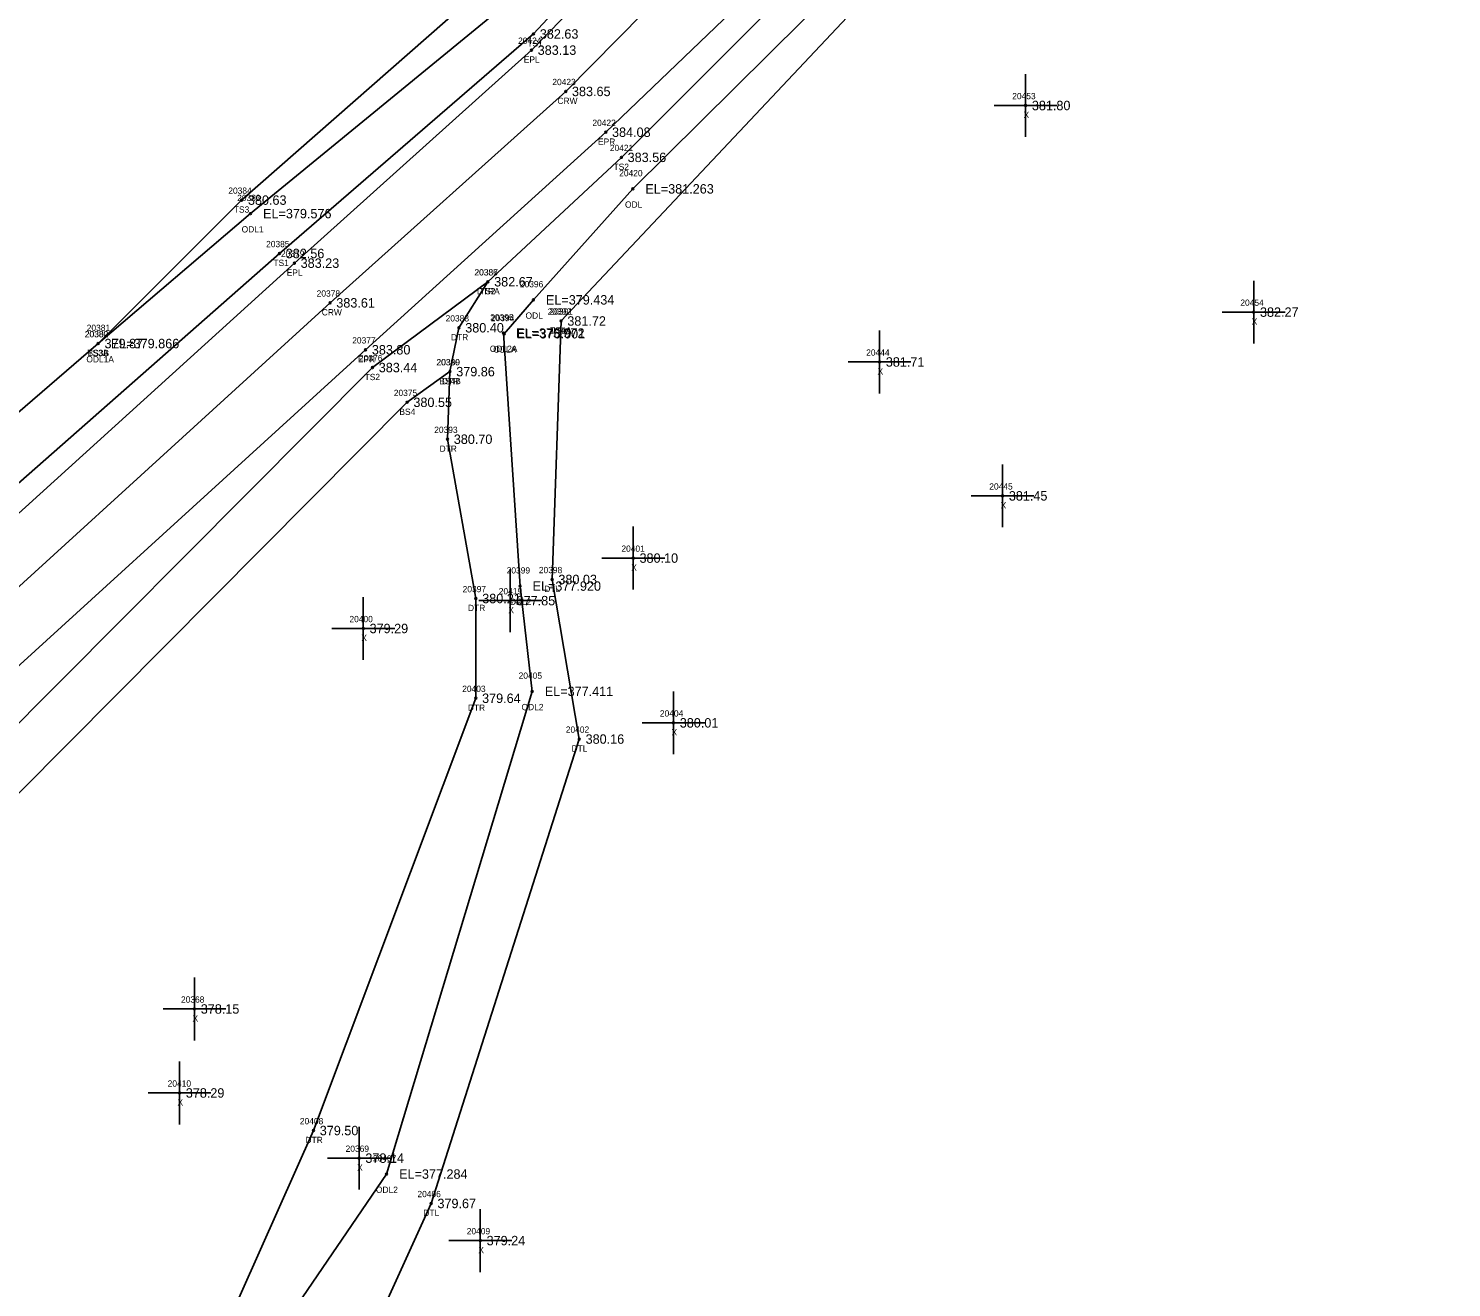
# Model space of a CAD drawing. Extents: x 2116373 to 2118139, y 979529 to 981026.
# Drawn here: x 2117649.6 to 2117875.9, y 980305.1 to 980505.4 of the extents above; entities that cross this region are included whole.
import ezdxf

# ---------------------------------------------------------------- set-up
doc = ezdxf.new("R2010")
doc.units = 0
for name, color, linetype in [('RD_DTM_BkLn1', 7, 'Continuous'), ('RD_DTM_BkLn2', 7, 'Continuous'), ('RD_DTM_BkLn_txCode', 7, 'Continuous'), ('RD_EX_H2O', 7, 'Continuous'), ('RD_EX_H2O_txCode', 7, 'Continuous'), ('RD_EX_Misc', 7, 'Continuous'), ('RD_EX_Misc_txCode', 7, 'Continuous'), ('RD_EX_Road', 7, 'Continuous'), ('RD_EX_Road_txCode', 7, 'Continuous'), ('RD_EX_TX_H2O_ELEV', 7, 'Continuous'), ('RD_EX_TX_Misc_ELEV', 7, 'Continuous'), ('RD_EX_TX_Road_ELEV', 7, 'Continuous'), ('RD_HC_Survey_ELEV', 7, 'Continuous'), ('RD_HC_Survey_txCode', 7, 'Continuous'), ('RD_SMD_Locator', 7, 'Continuous')]:
    doc.layers.add(name, color=color, linetype=linetype)

msp = doc.modelspace()

# ---------------------------------------------------------------- linework, layer by layer
at = {"layer": 'RD_DTM_BkLn1'}
msp.add_lwpolyline([(2117394.63, 980185.41), (2117475.35, 980259.39), (2117549.63, 980326.58), (2117623.5, 980394.2), (2117697.55, 980461.75), (2117735.02, 980495.39), (2117805.43, 980566.78), (2117837.53, 980605.36), (2117867.93, 980645.06), (2117897.09, 980686.34), (2117923.66, 980727.51), (2117948.72, 980771.39), (2117971.22, 980818.34), (2117988.96, 980866.05), (2117991.42, 980873.14), (2118004.26, 980915.09), (2118016.82, 980963.49), (2118028.02, 981013.26)], dxfattribs=at)
at = {"layer": 'RD_DTM_BkLn2'}
for points in [[(2117493.39, 980317.39), (2117496.3, 980311.64), (2117501.39, 980308.35), (2117540.21, 980337.44), (2117614.76, 980403.8), (2117689.51, 980469.61), (2117729.91, 980504.53), (2117761.86, 980538.86), (2117795.32, 980575.41), (2117828.25, 980612.61), (2117859.59, 980651.69), (2117887.1, 980692.35), (2117913.78, 980733.2), (2117937.24, 980777.08), (2117959.23, 980820.82), (2117978.84, 980869.89), (2117994.26, 980920.18), (2118007.51, 980964.57), (2118017.18, 981016.23)], [(2117403.18, 980177.15), (2117405.35, 980174.66), (2117487.26, 980245.43), (2117563.99, 980312.17), (2117634.65, 980381.46), (2117704.3, 980451.46), (2117722.65, 980465.11), (2117743.87, 980484.9), (2117780.03, 980521.07), (2117815.83, 980557.8), (2117846.79, 980597.78), (2117878.62, 980636.27), (2117911.26, 980677.34), (2117934.7, 980720.41), (2117959.82, 980759.29), (2117971.51, 980778.31), (2117986.8, 980774.26), (2117987.85, 980770.9), (2117995.22, 980745.17), (2118001.26, 980694.98), (2118008.4, 980640.04)], [(2117734.28, 980458.87), (2117786.65, 980514.59), (2117820.54, 980553.44), (2117855.54, 980590.41), (2117887.71, 980629.08), (2117918.16, 980671.7), (2117943.36, 980714.4), (2117971.9, 980758.61), (2117977.71, 980769.98), (2117980.03, 980767.32), (2117984.46, 980744.95), (2117988.75, 980693.43), (2117998.28, 980638.86)], [(2117660.7, 980455.28), (2117683.5, 980478.1), (2117721.89, 980511.88)], [(2117537.18, 980345.39), (2117608.78, 980410.55), (2117660.7, 980455.28)], [(2117389.45, 980162.29), (2117496.47, 980234.47), (2117570.67, 980306.14), (2117640.42, 980376.1), (2117709.81, 980445.93), (2117716.62, 980450.81)]]:
    msp.add_lwpolyline(points, dxfattribs=at)
at = {"layer": 'RD_EX_H2O'}
for points in [[(2117660.7, 980455.28), (2117684.91, 980475.95), (2117725.61, 980509.35), (2117716.83, 980529.54), (2117716.58, 980532.55), (2117726.37, 980536.81), (2117746.69, 980542.31), (2117751.04, 980554.04), (2117763.83, 980600.87), (2117795.75, 980642.32), (2117816.16, 980687.22), (2117820.4, 980726.27), (2117839.5, 980777.36), (2117872.08, 980815.27)], [(2117725.24, 980456.84), (2117729.88, 980462.23), (2117745.69, 980479.89), (2117783.52, 980517.46), (2117819.19, 980554.81), (2117852.43, 980593.07), (2117882.84, 980633.09), (2117913.27, 980675.65), (2117938.84, 980717.37), (2117963.41, 980761.5), (2117973.8, 980774.7), (2117982.58, 980769.22), (2117983.22, 980768.54), (2117990.51, 980745.52), (2117996.79, 980694.22), (2118004.21, 980639.35)], [(2117722.65, 980465.11), (2117718.05, 980457.79), (2117716.62, 980450.81), (2117716.23, 980440.06), (2117720.75, 980414.72), (2117720.73, 980398.85), (2117694.92, 980330.08), (2117677.85, 980291.74)], [(2117734.28, 980458.87), (2117732.86, 980417.75), (2117737.19, 980392.36), (2117713.63, 980318.48), (2117696.89, 980281.64)], [(2117725.14, 980456.95), (2117727.76, 980416.7), (2117729.7, 980399.95), (2117706.54, 980323.16), (2117683.8, 980289.78)]]:
    msp.add_lwpolyline(points, dxfattribs=at)
at = {"layer": 'RD_EX_Misc'}
for p, q in [((2117808.14, 980488.15), (2117808.14, 980498.15)), ((2117803.14, 980493.15), (2117813.14, 980493.15)), ((2117844.41, 980455.28), (2117844.41, 980465.28)), ((2117839.41, 980460.28), (2117849.41, 980460.28)), ((2117784.92, 980447.35), (2117784.92, 980457.35)), ((2117779.92, 980452.35), (2117789.92, 980452.35)), ((2117804.48, 980426.05), (2117804.48, 980436.05)), ((2117799.48, 980431.05), (2117809.48, 980431.05)), ((2117745.76, 980416.15), (2117745.76, 980426.15)), ((2117740.76, 980421.15), (2117750.76, 980421.15)), ((2117726.22, 980409.38), (2117726.22, 980419.38)), ((2117702.84, 980404.95), (2117702.84, 980414.95)), ((2117721.22, 980414.38), (2117731.22, 980414.38)), ((2117697.84, 980409.95), (2117707.84, 980409.95)), ((2117752.16, 980389.94), (2117752.16, 980399.94)), ((2117747.16, 980394.94), (2117757.16, 980394.94)), ((2117676, 980344.42), (2117676, 980354.42)), ((2117671, 980349.42), (2117681, 980349.42)), ((2117673.62, 980331.06), (2117673.62, 980341.06)), ((2117668.62, 980336.06), (2117678.62, 980336.06)), ((2117702.17, 980320.69), (2117702.17, 980330.69)), ((2117697.17, 980325.69), (2117707.17, 980325.69)), ((2117721.45, 980307.57), (2117721.45, 980317.57)), ((2117716.45, 980312.57), (2117726.45, 980312.57))]:
    msp.add_line(p, q, dxfattribs=at)
at = {"layer": 'RD_EX_Road'}
for points in [[(2117394.63, 980185.41), (2117388.45, 980192.75), (2117469.76, 980266.25), (2117487.02, 980282.1), (2117515.02, 980307.24), (2117543.53, 980333.04), (2117617.72, 980400.8), (2117691.88, 980468.07), (2117729.57, 980501.96), (2117798.93, 980572.83), (2117831.02, 980611), (2117861.69, 980650.07), (2117890.37, 980690.61), (2117916.67, 980731.93), (2117941.38, 980774.84), (2117963.75, 980821.95), (2117981.56, 980869.78), (2117996.2, 980917.73), (2118008.9, 980966.42), (2118019.55, 981015.46)], [(2117394.63, 980185.41), (2117401.85, 980177.36), (2117480.62, 980253.04), (2117556.27, 980319.95), (2117629.74, 980387.35), (2117703.2, 980454.29), (2117741.39, 980488.9), (2117777.53, 980523.58), (2117812.39, 980561.12), (2117844.66, 980599.64), (2117874.87, 980639.35), (2117904.78, 980681.4), (2117931.2, 980722.71), (2117957.05, 980767.35), (2117963.67, 980781.11), (2117980.28, 980814.62), (2117994.42, 980851.98)]]:
    msp.add_lwpolyline(points, dxfattribs=at)
at = {"layer": 'RD_SMD_Locator'}
for centre in [(2117729.91, 980504.53), (2117729.57, 980501.96), (2117735.02, 980495.39), (2117808.14, 980493.15), (2117741.39, 980488.9), (2117743.87, 980484.9), (2117745.69, 980479.89), (2117683.5, 980478.1), (2117684.91, 980475.95), (2117689.51, 980469.61), (2117691.88, 980468.07), (2117722.65, 980465.11), (2117722.65, 980465.11), (2117697.55, 980461.75), (2117729.88, 980462.23), (2117844.41, 980460.28), (2117718.05, 980457.79), (2117734.28, 980458.87), (2117734.28, 980458.87), (2117660.7, 980455.28), (2117660.7, 980455.28), (2117660.7, 980455.28), (2117725.14, 980456.95), (2117725.24, 980456.84), (2117703.2, 980454.29), (2117704.3, 980451.46), (2117716.62, 980450.81), (2117716.62, 980450.81), (2117784.92, 980452.35), (2117709.81, 980445.93), (2117716.23, 980440.06), (2117804.48, 980431.05), (2117745.76, 980421.15), (2117727.76, 980416.7), (2117732.86, 980417.75), (2117720.75, 980414.72), (2117726.22, 980414.38), (2117702.84, 980409.95), (2117720.73, 980398.85), (2117729.7, 980399.95), (2117752.16, 980394.94), (2117737.19, 980392.36), (2117676, 980349.42), (2117673.62, 980336.06), (2117694.92, 980330.08), (2117702.17, 980325.69), (2117706.54, 980323.16), (2117713.63, 980318.48), (2117721.45, 980312.57)]:
    msp.add_circle(centre, 0.15, dxfattribs=at)

# ---------------------------------------------------------------- texts
at = {"layer": 'RD_DTM_BkLn_txCode'}
for s, p in [('TS1', (2117728.95, 980502.53)), ('20421', (2117742.04, 980485.9)), ('TS2', (2117742.63, 980482.9)), ('20384', (2117681.38, 980479.1)), ('TS3', (2117682.26, 980476.1)), ('20385', (2117687.39, 980470.61)), ('TS1', (2117688.55, 980467.61)), ('20386', (2117720.5, 980466.11)), ('TS2', (2117721.4, 980463.11)), ('20392', (2117732.16, 980459.87)), ('20380', (2117658.55, 980456.28)), ('20382', (2117658.59, 980456.28)), ('TS4A', (2117732.55, 980456.87)), ('TS3A', (2117658.97, 980453.28)), ('BS3B', (2117659, 980453.28)), ('20376', (2117702.16, 980452.46)), ('20390', (2117714.46, 980451.81)), ('TS2', (2117703.05, 980449.46)), ('BS4B', (2117714.92, 980448.81)), ('20375', (2117707.69, 980446.93)), ('BS4', (2117708.58, 980443.93))]:
    msp.add_text(s, height=1, dxfattribs=at).set_placement(p)
at = {"layer": 'RD_EX_H2O_txCode'}
for s, p in [('20420', (2117743.53, 980481.89)), ('20383', (2117682.79, 980477.95)), ('ODL', (2117744.45, 980476.89)), ('ODL1', (2117683.5, 980472.95)), ('20387', (2117720.53, 980466.11)), ('DTRA', (2117720.89, 980463.11)), ('20396', (2117727.74, 980464.23)), ('20388', (2117715.93, 980458.79)), ('20395', (2117723.02, 980458.95)), ('20394', (2117723.13, 980458.84)), ('ODL', (2117728.64, 980459.23)), ('20391', (2117732.44, 980459.87)), ('20381', (2117658.87, 980457.28)), ('DTLA', (2117732.55, 980456.87)), ('DTR', (2117716.78, 980455.79)), ('ODL2A', (2117722.96, 980453.95)), ('ODLA', (2117723.51, 980453.84)), ('ODL1A', (2117658.81, 980452.28)), ('20389', (2117714.5, 980451.81)), ('DTR', (2117715.35, 980448.81)), ('20393', (2117714.12, 980441.06)), ('DTR', (2117714.97, 980438.06)), ('20399', (2117725.64, 980418.7)), ('20398', (2117730.75, 980418.75)), ('20397', (2117718.64, 980415.72)), ('DTL', (2117731.62, 980415.75)), ('ODL2', (2117726.07, 980413.7)), ('DTR', (2117719.49, 980412.72)), ('20405', (2117727.54, 980401.95)), ('20403', (2117718.57, 980399.85)), ('DTR', (2117719.46, 980396.85)), ('ODL2', (2117728, 980396.95)), ('20402', (2117735.04, 980393.36)), ('DTL', (2117735.95, 980390.36)), ('20408', (2117692.76, 980331.08)), ('DTR', (2117693.65, 980328.08)), ('20407', (2117704.38, 980325.16)), ('ODL2', (2117704.85, 980320.16)), ('20406', (2117711.45, 980319.48)), ('DTL', (2117712.39, 980316.48))]:
    msp.add_text(s, height=1, dxfattribs=at).set_placement(p)
at = {"layer": 'RD_EX_Misc_txCode'}
for s, p in [('20453', (2117806.02, 980494.15)), ('X', (2117807.82, 980491.15)), ('20454', (2117842.29, 980461.28)), ('X', (2117844.09, 980458.28)), ('20444', (2117782.8, 980453.35)), ('X', (2117784.61, 980450.35)), ('20445', (2117802.37, 980432.05)), ('X', (2117804.17, 980429.05)), ('20401', (2117743.88, 980422.15)), ('X', (2117745.44, 980419.15)), ('20419', (2117724.38, 980415.38)), ('20400', (2117700.64, 980410.95)), ('X', (2117725.9, 980412.38)), ('X', (2117702.53, 980407.95)), ('20404', (2117750, 980395.94)), ('X', (2117751.85, 980392.94)), ('20368', (2117673.86, 980350.42)), ('X', (2117675.69, 980347.42)), ('20410', (2117671.74, 980337.06)), ('X', (2117673.3, 980334.06)), ('20369', (2117700.03, 980326.69)), ('X', (2117701.86, 980323.69)), ('20409', (2117719.29, 980313.57)), ('X', (2117721.13, 980310.57))]:
    msp.add_text(s, height=1, dxfattribs=at).set_placement(p)
at = {"layer": 'RD_EX_Road_txCode'}
for s, p in [('20424', (2117727.45, 980502.96)), ('EPL', (2117728.36, 980499.96)), ('20422', (2117739.27, 980489.9)), ('EPR', (2117740.16, 980486.9)), ('20379', (2117689.76, 980469.07)), ('EPL', (2117690.67, 980466.07)), ('20377', (2117701.08, 980455.29)), ('EPR', (2117701.97, 980452.29))]:
    msp.add_text(s, height=1, dxfattribs=at).set_placement(p)
at = {"layer": 'RD_EX_TX_H2O_ELEV'}
for s, p in [('EL=381.263', (2117747.69, 980479.14)), ('EL=379.576', (2117686.91, 980475.2)), ('382.67', (2117723.65, 980464.36)), ('EL=379.434', (2117731.88, 980461.48)), ('381.72', (2117735.28, 980458.12)), ('380.40', (2117719.05, 980457.04)), ('EL=375.972', (2117727.14, 980456.2)), ('EL=376.001', (2117727.24, 980456.09)), ('EL=379.866', (2117662.7, 980454.53)), ('379.86', (2117717.62, 980450.06)), ('380.70', (2117717.23, 980439.31)), ('EL=377.920', (2117729.76, 980415.95)), ('380.03', (2117733.86, 980417)), ('380.21', (2117721.75, 980413.97)), ('EL=377.411', (2117731.7, 980399.2)), ('379.64', (2117721.73, 980398.1)), ('380.16', (2117738.19, 980391.61)), ('379.50', (2117695.92, 980329.33)), ('EL=377.284', (2117708.54, 980322.41)), ('379.67', (2117714.63, 980317.73))]:
    msp.add_text(s, height=1.5, dxfattribs=at).set_placement(p)
at = {"layer": 'RD_EX_TX_Misc_ELEV'}
for s, p in [('382.63', (2117730.91, 980503.78)), ('381.80', (2117809.14, 980492.4)), ('383.56', (2117744.87, 980484.15)), ('380.63', (2117684.5, 980477.35)), ('382.56', (2117690.51, 980468.86)), ('382.67', (2117723.65, 980464.36)), ('381.72', (2117735.28, 980458.12)), ('382.27', (2117845.41, 980459.53)), ('379.87', (2117661.7, 980454.53)), ('379.87', (2117661.7, 980454.53)), ('381.71', (2117785.92, 980451.6)), ('383.44', (2117705.3, 980450.71)), ('379.86', (2117717.62, 980450.06)), ('380.55', (2117710.81, 980445.18)), ('381.45', (2117805.48, 980430.3)), ('380.10', (2117746.76, 980420.4)), ('377.85', (2117727.22, 980413.63)), ('379.29', (2117703.84, 980409.2)), ('380.01', (2117753.16, 980394.19)), ('378.15', (2117677, 980348.67)), ('378.29', (2117674.62, 980335.31)), ('378.14', (2117703.17, 980324.94)), ('379.24', (2117722.45, 980311.82))]:
    msp.add_text(s, height=1.5, dxfattribs=at).set_placement(p)
at = {"layer": 'RD_EX_TX_Road_ELEV'}
for s, p in [('383.13', (2117730.57, 980501.21)), ('384.08', (2117742.39, 980488.15)), ('383.23', (2117692.88, 980467.32)), ('383.80', (2117704.2, 980453.54))]:
    msp.add_text(s, height=1.5, dxfattribs=at).set_placement(p)
at = {"layer": 'RD_HC_Survey_ELEV'}
for s, p in [('383.65', (2117736.02, 980494.64)), ('383.61', (2117698.55, 980461))]:
    msp.add_text(s, height=1.5, dxfattribs=at).set_placement(p)
at = {"layer": 'RD_HC_Survey_txCode'}
for s, p in [('20423', (2117732.9, 980496.39)), ('CRW', (2117733.71, 980493.39)), ('20378', (2117695.43, 980462.75)), ('CRW', (2117696.24, 980459.75))]:
    msp.add_text(s, height=1, dxfattribs=at).set_placement(p)

doc.saveas('drawing.dxf')
